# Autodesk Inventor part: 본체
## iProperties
Company: 한국ATC센터
Created: 2015-04
Part Number: 본체
Document SubType Name: Modeling
Designer: KYOUNG IL JANG
Density: 1 g/cm^3
Material: 기본값
Mass: 494.771 g
Surface Area: 1387.34 cm^2
Volume: 494.771 cm^3
Author: KYOUNG IL JANG
